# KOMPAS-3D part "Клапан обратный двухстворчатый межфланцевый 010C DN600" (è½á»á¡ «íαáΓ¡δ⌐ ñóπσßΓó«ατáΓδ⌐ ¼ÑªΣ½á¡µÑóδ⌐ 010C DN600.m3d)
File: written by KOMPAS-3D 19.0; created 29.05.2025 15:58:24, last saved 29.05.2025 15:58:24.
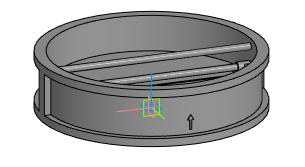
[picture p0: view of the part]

Document properties: Полное имя файла: E:\Dendor Работа Сачек\3D для проекитирвщиков\5.2 Тип 010C, 010C.Y Клапан обратный двухстворчатый межфланцевый\stp_Клапан обратный двухстворчатый межфланцевый 010C\Клапан обратный двухстворчатый межфланцевый 010C DN600.m3d

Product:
- Part/product: Клапан обратный двухстворчатый межфланцевый 010C DN600

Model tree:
1. Операция без истории:1  (labels: Клапан обратный двухстворчатый межфланцевый 010C DN600)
